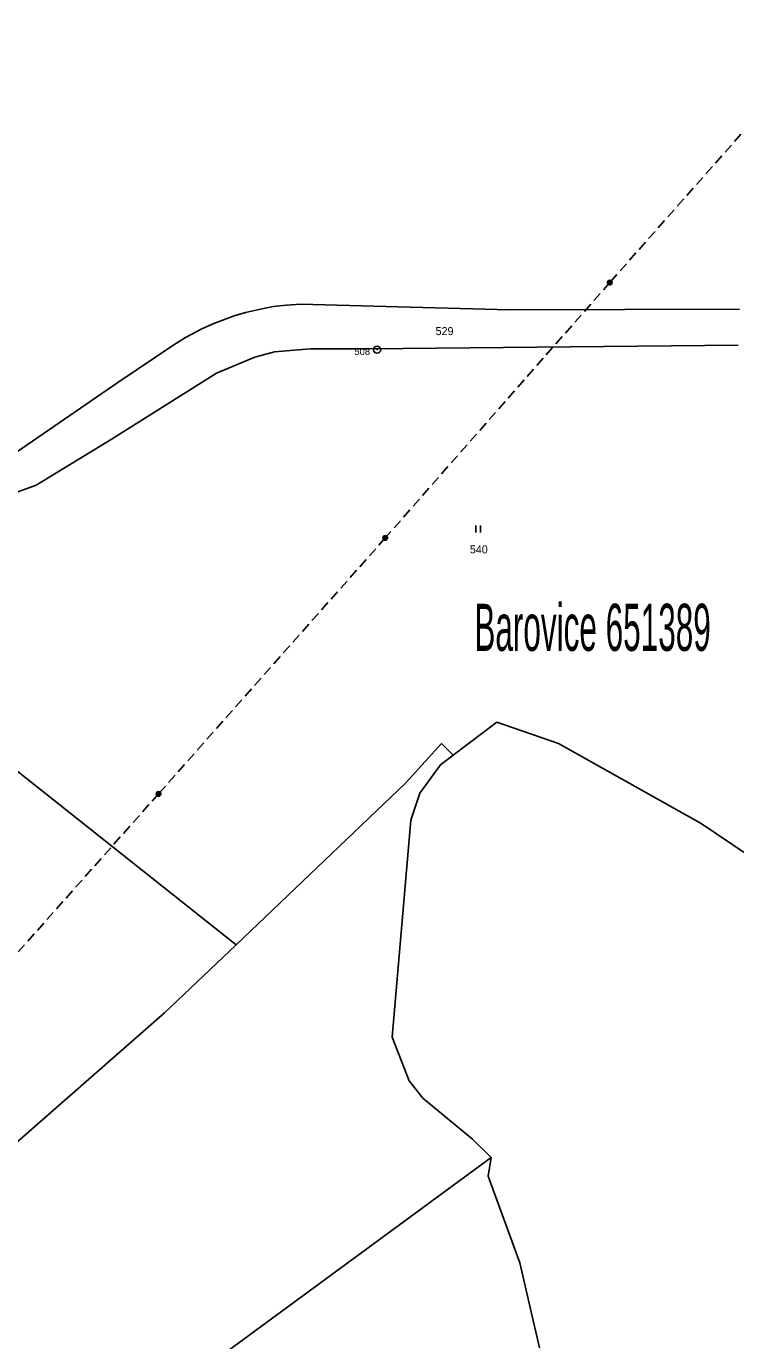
# Model space of a CAD drawing. Extents: x -653193 to -651624, y -1092017 to -1090260.
# Drawn here: x -652559.8 to -652409.3, y -1091426.8 to -1091147.6 of the extents above; entities that cross this region are included whole.
import ezdxf
from ezdxf.enums import TextEntityAlignment as Align

# ---------------------------------------------------------------- set-up
doc = ezdxf.new("R2010")
doc.units = 0
doc.header["$LTSCALE"] = 0.68
doc.linetypes.add('MEDIUM_DASHED', pattern=[4.5, 3, -1.5])
for name, color, linetype, lineweight in [('1', 7, 'Continuous', 25), ('3', 7, 'Continuous', 25), ('6', 7, 'Continuous', 25), ('7', 7, 'Continuous', 13), ('8', 7, 'Continuous', 25)]:
    doc.layers.add(name, color=color, linetype=linetype, lineweight=lineweight)
doc.layers.add('2', color=7, linetype='Continuous')

msp = doc.modelspace()

# ---------------------------------------------------------------- linework, layer by layer
at = {"layer": '1'}
for p, q in [((-652510.07, -1091207.66), (-652513.27, -1091208.42)), ((-652507.38, -1091207.16), (-652510.07, -1091207.66)), ((-652504.58, -1091206.82), (-652507.38, -1091207.16)), ((-652501.56, -1091206.62), (-652504.58, -1091206.82)), ((-652483.52, -1091207.11), (-652501.56, -1091206.62)), ((-652457.25, -1091207.83), (-652483.52, -1091207.11)), ((-652408.46, -1091207.73), (-652457.25, -1091207.83)), ((-652519.99, -1091210.74), (-652522.42, -1091211.79)), ((-652515.71, -1091209.11), (-652519.99, -1091210.74)), ((-652513.27, -1091208.42), (-652515.71, -1091209.11)), ((-652526.04, -1091213.72), (-652528.67, -1091215.4)), ((-652522.42, -1091211.79), (-652526.04, -1091213.72)), ((-652528.67, -1091215.4), (-652540.35, -1091223.27)), ((-652499.5, -1091216.13), (-652507.12, -1091216.78)), ((-652486.99, -1091216.11), (-652499.5, -1091216.13)), ((-652408.71, -1091215.36), (-652486.99, -1091216.11)), ((-652511.33, -1091217.89), (-652519.46, -1091221.29)), ((-652507.12, -1091216.78), (-652511.33, -1091217.89)), ((-652519.46, -1091221.29), (-652541.57, -1091235.2)), ((-652540.35, -1091223.27), (-652563.01, -1091238.81)), ((-652541.57, -1091235.2), (-652557.72, -1091245.07)), ((-652557.72, -1091245.07), (-652568.28, -1091248.96)), ((-652459.91, -1091295.37), (-652469.18, -1091302.43)), ((-652446.85, -1091299.95), (-652459.91, -1091295.37)), ((-652479.33, -1091308.38), (-652471.66, -1091299.92)), ((-652471.66, -1091299.92), (-652469.18, -1091302.43)), ((-652416.58, -1091316.92), (-652446.85, -1091299.95)), ((-652469.18, -1091302.43), (-652471.88, -1091304.49)), ((-652515.29, -1091342.68), (-652561.87, -1091305.65)), ((-652471.88, -1091304.49), (-652476.29, -1091310.5)), ((-652515.29, -1091342.68), (-652479.33, -1091308.38)), ((-652476.29, -1091310.5), (-652478.22, -1091316.21)), ((-652478.22, -1091316.21), (-652482.13, -1091362.28)), ((-652403.34, -1091325.86), (-652416.58, -1091316.92)), ((-652530.45, -1091357.14), (-652515.29, -1091342.68)), ((-652581.06, -1091401.45), (-652530.45, -1091357.14)), ((-652482.13, -1091362.28), (-652478.57, -1091371.55)), ((-652478.57, -1091371.55), (-652475.63, -1091375.29)), ((-652475.63, -1091375.29), (-652465.12, -1091383.96)), ((-652465.12, -1091383.96), (-652461.12, -1091387.85)), ((-652461.12, -1091387.85), (-652551.95, -1091454.53)), ((-652461.12, -1091387.85), (-652461.81, -1091391.85)), ((-652461.81, -1091391.85), (-652455.08, -1091410.25)), ((-652455.08, -1091410.25), (-652450.86, -1091428.27))]:
    msp.add_line(p, q, dxfattribs=at)
at = {"layer": '3'}
for p, q in [((-652464.381, -1091255.11), (-652464.381, -1091253.61)), ((-652463.38, -1091255.11), (-652463.38, -1091253.61))]:
    msp.add_line(p, q, dxfattribs=at)
at = {"layer": '6', "linetype": 'MEDIUM_DASHED'}
for p, q in [((-652387.86, -1091147.62), (-652435.98, -1091202.04)), ((-652435.98, -1091202.04), (-652483.62, -1091256.27)), ((-652483.62, -1091256.27), (-652531.73, -1091310.63)), ((-652531.73, -1091310.63), (-652580.43, -1091365.53))]:
    msp.add_line(p, q, dxfattribs=at)
at = {"layer": '6'}
for centre, radius in [((-652435.9834, -1091202.0399), 0.5), ((-652435.9834, -1091202.0399), 0.4), ((-652435.9834, -1091202.0399), 0.3), ((-652435.9834, -1091202.0399), 0.2), ((-652435.9834, -1091202.0399), 0.1), ((-652483.6234, -1091256.2699), 0.5), ((-652483.6234, -1091256.2699), 0.4), ((-652483.6234, -1091256.2699), 0.3), ((-652483.6234, -1091256.2699), 0.2), ((-652483.6234, -1091256.2699), 0.1), ((-652531.7334, -1091310.6299), 0.5), ((-652531.7334, -1091310.6299), 0.4), ((-652531.7334, -1091310.6299), 0.3), ((-652531.7334, -1091310.6299), 0.2), ((-652531.7334, -1091310.6299), 0.1)]:
    msp.add_circle(centre, radius, dxfattribs=at)
at = {"layer": '8'}
for radius in [0.75, 0.03]:
    msp.add_circle((-652485.34, -1091216.3098), radius, dxfattribs=at)

# ---------------------------------------------------------------- texts
at = {"layer": '2'}
for s, p in [('529', (-652471.039, -1091213.205)), ('540', (-652463.769, -1091259.555))]:
    msp.add_text(s, height=1.7, dxfattribs=at).set_placement(p, align=Align.CENTER)
at = {"layer": '7', "width": 0.5}
msp.add_text('Barovice 651389', height=10, dxfattribs=at).set_placement((-652439.629, -1091280.263), align=Align.CENTER)
at = {"layer": '8'}
msp.add_text('508', height=1.5, dxfattribs=at).set_placement((-652486.839, -1091217.427), align=Align.RIGHT)

doc.saveas('drawing.dxf')
